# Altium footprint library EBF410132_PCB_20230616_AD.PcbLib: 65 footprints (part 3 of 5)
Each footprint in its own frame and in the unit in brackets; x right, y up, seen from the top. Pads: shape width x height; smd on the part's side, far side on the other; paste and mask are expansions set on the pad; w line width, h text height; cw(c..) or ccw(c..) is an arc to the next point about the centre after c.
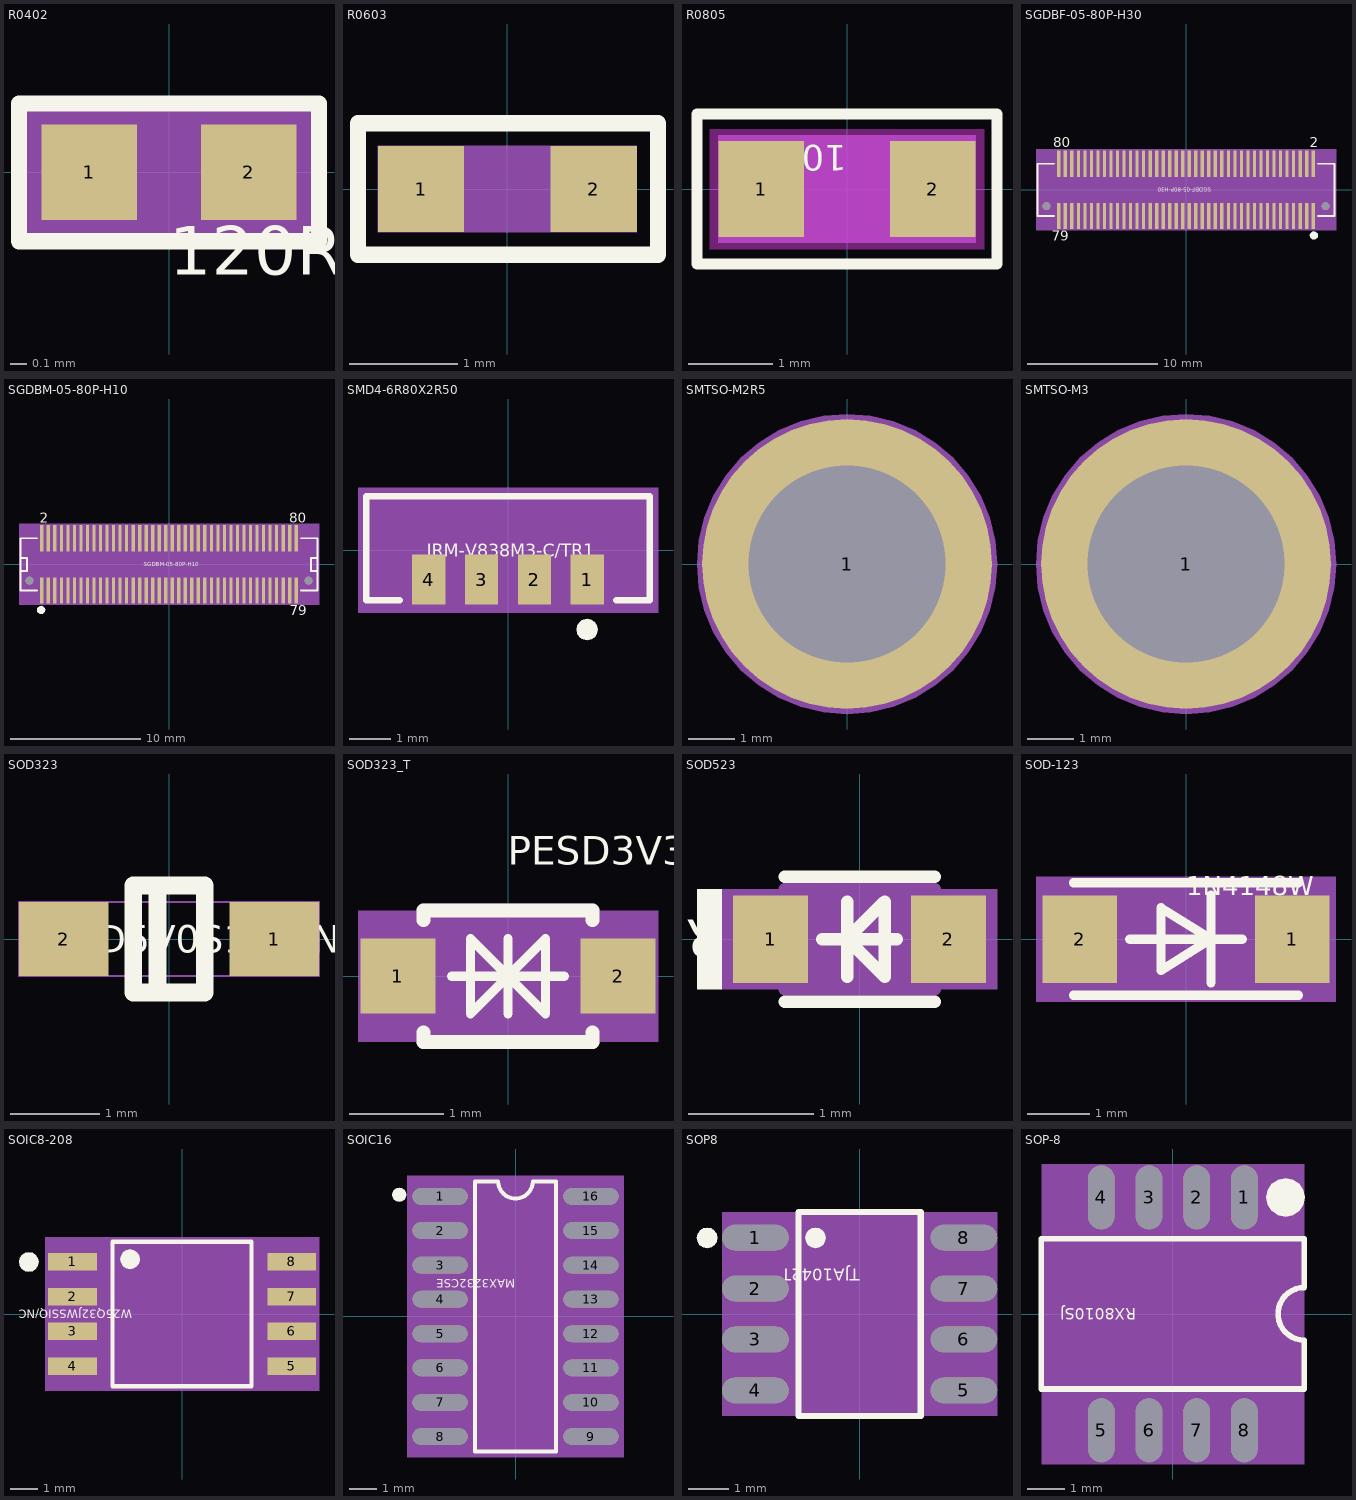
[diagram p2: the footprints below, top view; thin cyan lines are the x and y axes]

## R0402 [mm] "R0402"
pads (2):
  rect 0.599x0.599 smd: 1(-0.5,0) 2(0.5,0)
Top Overlay:
  lines w0.102: -0.94,-0.432 0.94,-0.432 0.94,0.432 -0.94,0.432 -0.94,-0.432
  text "120R" at 0,-0.64 h0.3
Top 3D Body:
  region: 0.94,0.432 0.94,-0.432 -0.94,-0.432 -0.94,0.432
Mechanical 15:
  text "2" at 0.5,-0.254 h0.64
  text "1" at -0.5,-0.254 h0.64
Top Assembly:
  dashed: -0.94,-0.432 -0.94,0.432 0.94,0.432 0.94,-0.432
3D body: height 3.81, standoff 0, extent -0.94,-0.432 0.94,0.432

## R0603 [mil] "R0603"
pads (2):
  rect 31.5x31.5 smd: 1(-31.5,0) 2(31.5,0)
Top Overlay:
  lines w6: -54.5,-24 55,-24 55,24 -54.5,24 -54.5,-24
  text "10K" at -14.4,6 h12
Top 3D Body:
  region: -47.24,-15.75 -47.24,15.75 47.24,15.75 47.24,-15.75
Mechanical 15:
  text "1" at -49.5,0 h45
  text "2" at 13.5,0 h45
3D body: height 150, standoff 0, extent -47.24,-15.75 47.24,15.75

## R0805 [mil] "R0805"
pads (2):
  rect 40x45 smd: 1(-40,0) 2(40,0)
Top Overlay:
  lines w5: -70,-35 70,-35 70,35 -70,35 -70,-35
  text "10R" at -0.01,20.4 h12
Top 3D Body:
  region: -60,25 60,25 60,-25 -60,-25
Mechanical 15:
  text "2" at 40,12 h30
  text "1" at -40,12 h30
Top Assembly:
  text "R0805" at -115,45 h25
Multi-Layer keep-out:
  region: -64,-28 -64,28 64,28 64,-28
3D body: height 150, standoff 0, extent -60,-25 60,25

## SGDBF-05-80P-H30 [mm] "SGDBF-05-80P-H30"
pads (82):
  rect 0.25x2 smd: 1(9.75,-2) 2(9.75,2) 3(9.25,-2) 4(9.25,2) 5(8.75,-2) 6(8.75,2) 7(8.25,-2) 8(8.25,2) 9(7.75,-2) 10(7.75,2) 11(7.25,-2) 12(7.25,2) 13(6.75,-2) 14(6.75,2) 15(6.25,-2) 16(6.25,2) 17(5.75,-2) 18(5.75,2) 19(5.25,-2) 20(5.25,2) 21(4.75,-2) 22(4.75,2) 23(4.25,-2) 24(4.25,2) 25(3.75,-2) 26(3.75,2) 27(3.25,-2) 28(3.25,2) 29(2.75,-2) 30(2.75,2) 31(2.25,-2) 32(2.25,2) 33(1.75,-2) 34(1.75,2) 35(1.25,-2) 36(1.25,2) 37(0.75,-2) 38(0.75,2) 39(0.25,-2) 40(0.25,2) 41(-0.25,-2) 42(-0.25,2) 43(-0.75,-2) 44(-0.75,2) 45(-1.25,-2) 46(-1.25,2) 47(-1.75,-2) 48(-1.75,2) 49(-2.25,-2) 50(-2.25,2) 51(-2.75,-2) 52(-2.75,2) 53(-3.25,-2) 54(-3.25,2) 55(-3.75,-2) 56(-3.75,2) 57(-4.25,-2) 58(-4.25,2) 59(-4.75,-2) 60(-4.75,2) 61(-5.25,-2) 62(-5.25,2) 63(-5.75,-2) 64(-5.75,2) 65(-6.25,-2) 66(-6.25,2) 67(-6.75,-2) 68(-6.75,2) 69(-7.25,-2) 70(-7.25,2) 71(-7.75,-2) 72(-7.75,2) 73(-8.25,-2) 74(-8.25,2) 75(-8.75,-2) 76(-8.75,2) 77(-9.25,-2) 78(-9.25,2) 79(-9.75,-2) 80(-9.75,2)
  round 0.6 hole 0.6 unplated: ""(-10.7,-1.25) ""(10.7,-1.25)
Top Overlay:
  dashed: 9.494,-3.5 9.517,-3.617 9.584,-3.716 9.683,-3.783 9.8,-3.806 9.917,-3.783 9.95,-3.76 10.016,-3.716 10.083,-3.617 10.106,-3.5 10.083,-3.383 10.016,-3.284 9.95,-3.24 9.917,-3.217 9.8,-3.194 9.683,-3.217 9.584,-3.284 9.517,-3.383
  lines w0.15: -10.1,-2 -11.4,-2 -11.4,2 -10.1,2 ; 10.1,-2 11.4,-2 11.4,2 10.1,2
  text "SGDBF-05-80P-H30" at 1.951,0.152 h0.3
  text "80" at -10.183,3.282 h0.76
  text "2" at 9.497,3.282 h0.76
  text "79" at -10.283,-3.917 h0.76
Top 3D Body:
  region: 11.5,-3.1 11.5,3.1 -11.5,3.1 -11.5,-3.1
Mechanical 15:
  text "15" at 6.758,-2 h0.64
  text "13" at 7.258,-2 h0.64
  text "17" at 6.258,-2 h0.64
  text "10" at 8.258,2 h0.64
  text "4" at 9.504,2 h0.64
  text "8" at 8.504,2 h0.64
  text "39" at 0.758,-2 h0.64
  text "56" at -3.242,2 h0.64
  text "59" at -4.242,-2 h0.64
  text "60" at -4.242,2 h0.64
  text "30" at 3.258,2 h0.64
  text "51" at -2.242,-2 h0.64
  text "44" at -0.242,2 h0.64
  text "37" at 1.258,-2 h0.64
  text "62" at -4.742,2 h0.64
  text "66" at -5.742,2 h0.64
  text "25" at 4.258,-2 h0.64
  text "27" at 3.758,-2 h0.64
  text "7" at 8.504,-2 h0.64
  text "68" at -6.242,2 h0.64
  text "9" at 8.004,-2 h0.64
  text "43" at -0.242,-2 h0.64
  text "12" at 7.758,2 h0.64
  text "33" at 2.258,-2 h0.64
  text "23" at 4.758,-2 h0.64
  text "79" at -9.242,-2 h0.64
  text "75" at -8.242,-2 h0.64
  text "77" at -8.742,-2 h0.64
  text "73" at -7.742,-2 h0.64
  text "71" at -7.242,-2 h0.64
  text "69" at -6.742,-2 h0.64
  text "1" at 10.004,-2 h0.64
  text "78" at -8.742,2 h0.64
  text "80" at -9.242,2 h0.64
  text "2" at 10.004,2 h0.64
  text "26" at 4.258,2 h0.64
  text "40" at 0.758,2 h0.64
  text "54" at -2.742,2 h0.64
  text "58" at -3.742,2 h0.64
  text "64" at -5.242,2 h0.64
  text "70" at -6.742,2 h0.64
  text "76" at -8.242,2 h0.64
  text "74" at -7.742,2 h0.64
  text "72" at -7.242,2 h0.64
  text "67" at -6.242,-2 h0.64
  text "61" at -4.742,-2 h0.64
  text "65" at -5.742,-2 h0.64
  text "11" at 7.758,-2 h0.64
  text "41" at 0.258,-2 h0.64
  text "57" at -3.742,-2 h0.64
  text "55" at -3.242,-2 h0.64
  text "53" at -2.742,-2 h0.64
  text "49" at -1.742,-2 h0.64
  text "21" at 5.258,-2 h0.64
  text "19" at 5.758,-2 h0.64
  text "5" at 9.004,-2 h0.64
  text "3" at 9.504,-2 h0.64
  text "45" at -0.742,-2 h0.64
  text "63" at -5.242,-2 h0.64
  text "42" at 0.258,2 h0.64
  text "46" at -0.742,2 h0.64
  text "48" at -1.242,2 h0.64
  text "50" at -1.742,2 h0.64
  text "52" at -2.242,2 h0.64
  text "38" at 1.258,2 h0.64
  text "36" at 1.758,2 h0.64
  text "28" at 3.758,2 h0.64
  text "32" at 2.758,2 h0.64
  text "34" at 2.258,2 h0.64
  text "47" at -1.242,-2 h0.64
  text "6" at 9.004,2 h0.64
  text "35" at 1.758,-2 h0.64
  text "31" at 2.758,-2 h0.64
  text "29" at 3.258,-2 h0.64
  text "24" at 4.758,2 h0.64
  text "22" at 5.258,2 h0.64
  text "20" at 5.758,2 h0.64
  text "18" at 6.258,2 h0.64
  text "16" at 6.758,2 h0.64
  text "14" at 7.258,2 h0.64
Top Assembly:
  lines w0.15: -11.4,-2 11.4,-2 11.4,2 -11.4,2 -11.4,-2
3D body: height 3.81, standoff 0, extent -11.5,-3.1 11.5,3.1

## SGDBM-05-80P-H10 [mm] "SGDBM-05-80P-H10"
pads (82):
  rect 0.25x2 smd: 1(-9.75,-2) 2(-9.75,2) 3(-9.25,-2) 4(-9.25,2) 5(-8.75,-2) 6(-8.75,2) 7(-8.25,-2) 8(-8.25,2) 9(-7.75,-2) 10(-7.75,2) 11(-7.25,-2) 12(-7.25,2) 13(-6.75,-2) 14(-6.75,2) 15(-6.25,-2) 16(-6.25,2) 17(-5.75,-2) 18(-5.75,2) 19(-5.25,-2) 20(-5.25,2) 21(-4.75,-2) 22(-4.75,2) 23(-4.25,-2) 24(-4.25,2) 25(-3.75,-2) 26(-3.75,2) 27(-3.25,-2) 28(-3.25,2) 29(-2.75,-2) 30(-2.75,2) 31(-2.25,-2) 32(-2.25,2) 33(-1.75,-2) 34(-1.75,2) 35(-1.25,-2) 36(-1.25,2) 37(-0.75,-2) 38(-0.75,2) 39(-0.25,-2) 40(-0.25,2) 41(0.25,-2) 42(0.25,2) 43(0.75,-2) 44(0.75,2) 45(1.25,-2) 46(1.25,2) 47(1.75,-2) 48(1.75,2) 49(2.25,-2) 50(2.25,2) 51(2.75,-2) 52(2.75,2) 53(3.25,-2) 54(3.25,2) 55(3.75,-2) 56(3.75,2) 57(4.25,-2) 58(4.25,2) 59(4.75,-2) 60(4.75,2) 61(5.25,-2) 62(5.25,2) 63(5.75,-2) 64(5.75,2) 65(6.25,-2) 66(6.25,2) 67(6.75,-2) 68(6.75,2) 69(7.25,-2) 70(7.25,2) 71(7.75,-2) 72(7.75,2) 73(8.25,-2) 74(8.25,2) 75(8.75,-2) 76(8.75,2) 77(9.25,-2) 78(9.25,2) 79(9.75,-2) 80(9.75,2)
  round 0.6 hole 0.6 unplated: ""(-10.7,-1.25) ""(10.7,-1.25)
Top Overlay:
  dashed: -9.494,-3.5 -9.517,-3.383 -9.584,-3.284 -9.683,-3.217 -9.8,-3.194 -9.917,-3.217 -9.95,-3.24 -10.016,-3.284 -10.083,-3.383 -10.106,-3.5 -10.083,-3.617 -10.016,-3.716 -9.95,-3.76 -9.917,-3.783 -9.8,-3.806 -9.683,-3.783 -9.584,-3.716 -9.517,-3.617
  lines w0.15: -11.4,0 -11.4,-0.5 -10.9,-0.5 -10.9,0.5 -11.4,0.5 ; -10.1,-2 -11.4,-2 -11.4,2 -10.1,2 ; 10.1,-2 11.4,-2 11.4,2 10.1,2 ; 11.4,0 11.4,-0.5 10.9,-0.5 10.9,0.5 11.4,0.5
  text "SGDBM-05-80P-H10" at -1.951,-0.152 h0.3
  text "2" at -9.903,3.182 h0.76
  text "79" at 9.268,-3.895 h0.76
  text "80" at 9.217,3.182 h0.76
Top 3D Body:
  region: -11.5,3.1 -11.5,-3.1 11.5,-3.1 11.5,3.1
Mechanical 15:
  text "32" at -2.758,2 h0.64
  text "34" at -2.258,2 h0.64
  text "36" at -1.758,2 h0.64
  text "38" at -1.258,2 h0.64
  text "50" at 1.742,2 h0.64
  text "52" at 2.242,2 h0.64
  text "54" at 2.742,2 h0.64
  text "56" at 3.242,2 h0.64
  text "28" at -3.758,2 h0.64
  text "26" at -4.258,2 h0.64
  text "24" at -4.758,2 h0.64
  text "22" at -5.258,2 h0.64
  text "62" at 4.742,2 h0.64
  text "60" at 4.242,2 h0.64
  text "15" at -6.758,-2 h0.64
  text "10" at -8.258,2 h0.64
  text "9" at -8.004,-2 h0.64
  text "7" at -8.504,-2 h0.64
  text "18" at -6.258,2 h0.64
  text "14" at -7.258,2 h0.64
  text "30" at -3.258,2 h0.64
  text "64" at 5.242,2 h0.64
  text "40" at -0.758,2 h0.64
  text "68" at 6.242,2 h0.64
  text "58" at 3.742,2 h0.64
  text "1" at -10.004,-2 h0.64
  text "79" at 9.242,-2 h0.64
  text "75" at 8.242,-2 h0.64
  text "11" at -7.758,-2 h0.64
  text "27" at -3.758,-2 h0.64
  text "41" at -0.258,-2 h0.64
  text "55" at 3.242,-2 h0.64
  text "69" at 6.742,-2 h0.64
  text "2" at -10.004,2 h0.64
  text "8" at -8.504,2 h0.64
  text "77" at 8.742,-2 h0.64
  text "20" at -5.758,2 h0.64
  text "59" at 4.242,-2 h0.64
  text "42" at -0.258,2 h0.64
  text "21" at -5.258,-2 h0.64
  text "48" at 1.242,2 h0.64
  text "66" at 5.742,2 h0.64
  text "46" at 0.742,2 h0.64
  text "71" at 7.242,-2 h0.64
  text "44" at 0.242,2 h0.64
  text "73" at 7.742,-2 h0.64
  text "17" at -6.258,-2 h0.64
  text "51" at 2.242,-2 h0.64
  text "53" at 2.742,-2 h0.64
  text "19" at -5.758,-2 h0.64
  text "43" at 0.242,-2 h0.64
  text "13" at -7.258,-2 h0.64
  text "45" at 0.742,-2 h0.64
  text "47" at 1.242,-2 h0.64
  text "25" at -4.258,-2 h0.64
  text "16" at -6.758,2 h0.64
  text "49" at 1.742,-2 h0.64
  text "23" at -4.758,-2 h0.64
  text "72" at 7.242,2 h0.64
  text "61" at 4.742,-2 h0.64
  text "63" at 5.242,-2 h0.64
  text "65" at 5.742,-2 h0.64
  text "67" at 6.242,-2 h0.64
  text "5" at -9.004,-2 h0.64
  text "3" at -9.504,-2 h0.64
  text "39" at -0.758,-2 h0.64
  text "33" at -2.258,-2 h0.64
  text "35" at -1.758,-2 h0.64
  text "31" at -2.758,-2 h0.64
  text "29" at -3.258,-2 h0.64
  text "76" at 8.242,2 h0.64
  text "37" at -1.258,-2 h0.64
  text "12" at -7.758,2 h0.64
  text "57" at 3.742,-2 h0.64
  text "80" at 9.242,2 h0.64
  text "78" at 8.742,2 h0.64
  text "70" at 6.742,2 h0.64
  text "4" at -9.504,2 h0.64
  text "6" at -9.004,2 h0.64
  text "74" at 7.742,2 h0.64
Top Assembly:
  lines w0.15: -11.4,-2 11.4,-2 11.4,2 -11.4,2 -11.4,-2
3D body: height 3.81, standoff 0, extent -11.5,-3.1 11.5,3.1

## SMD4-6R80X2R50 [mm] "SMD4-6R80X2R50"
pads (4):
  rect 0.8x1.2 smd: 1(1.905,-0.7) 2(0.635,-0.7) 3(-0.635,-0.7) 4(-1.905,-0.7)
Top Overlay:
  dashed: 2.155,-1.9 2.136,-1.802 2.08,-1.72 1.998,-1.664 1.9,-1.645 1.802,-1.664 1.775,-1.683 1.72,-1.72 1.664,-1.802 1.645,-1.9 1.664,-1.998 1.72,-2.08 1.775,-2.117 1.802,-2.136 1.9,-2.155 1.998,-2.136 2.08,-2.08 2.136,-1.998
  lines w0.15: -2.6,-1.2 -3.4,-1.2 -3.4,1.3 3.4,1.3 3.4,-1.2 2.6,-1.2
  text "IRM-V838M3-C/TR1" at -1.951,-0.152 h0.3
Top 3D Body:
  region: -3.6,1.5 -3.6,-1.5 3.6,-1.5 3.6,1.5
Mechanical 15:
  text "4" at -2.159,-0.7 h0.64
  text "1" at 1.651,-0.7 h0.64
  text "2" at 0.381,-0.7 h0.64
  text "3" at -0.889,-0.7 h0.64
Top Assembly:
  lines w0.15: -3.4,-1.2 3.4,-1.2 3.4,1.3 -3.4,1.3 -3.4,-1.2
3D body: height 3.81, standoff 0, extent -3.6,-1.5 3.6,1.5

## SMTSO-M2R5 [mm] "SMTSO-M2R5"
pads (1):
  round 6.2 / inner round 5.2 / far side round 5.2 hole 4.22: 1(0,0)
Top Overlay:
  text "M2.5X4mm" at -0.975,-0.152 h0.3
Top 3D Body:
  region: 3.21,0 3.17,0.502 3.053,0.992 2.86,1.457 2.597,1.887 2.27,2.27 1.887,2.597 1.457,2.86 0.992,3.053 0.502,3.17 0,3.21 -0.502,3.17 -0.992,3.053 -1.457,2.86 -1.601,2.772 -1.887,2.597 -2.27,2.27 -2.597,1.887 -2.86,1.457 -3.053,0.992 -3.17,0.502 -3.21,0 -3.17,-0.502 -3.053,-0.992 -2.86,-1.457 -2.597,-1.887 -2.27,-2.27 -1.887,-2.597 -1.601,-2.772 -1.457,-2.86 -0.992,-3.053 -0.502,-3.17 0,-3.21 0.502,-3.17 0.992,-3.053 1.457,-2.86 1.887,-2.597 2.27,-2.27 2.597,-1.887 2.86,-1.457 3.053,-0.992 3.17,-0.502
Mechanical 15:
  text "1" at -0.254,0 h0.64
3D body: height 3.81, standoff 0, extent -3.21,-3.21 3.21,3.21

## SMTSO-M3 [mm] "SMTSO-M3"
pads (1):
  round 6.2 / inner round 5.2 / far side round 5.2 hole 4.22: 1(0,0)
Top Overlay:
  text "M3X3.5mm" at -0.975,-0.152 h0.3
Top 3D Body:
  region: 3.21,0 3.17,0.502 3.053,0.992 2.86,1.457 2.597,1.887 2.27,2.27 1.887,2.597 1.457,2.86 0.992,3.053 0.502,3.17 0,3.21 -0.502,3.17 -0.992,3.053 -1.457,2.86 -1.601,2.772 -1.887,2.597 -2.27,2.27 -2.597,1.887 -2.86,1.457 -3.053,0.992 -3.17,0.502 -3.21,0 -3.17,-0.502 -3.053,-0.992 -2.86,-1.457 -2.597,-1.887 -2.27,-2.27 -1.887,-2.597 -1.601,-2.772 -1.457,-2.86 -0.992,-3.053 -0.502,-3.17 0,-3.21 0.502,-3.17 0.992,-3.053 1.457,-2.86 1.887,-2.597 2.27,-2.27 2.597,-1.887 2.86,-1.457 3.053,-0.992 3.17,-0.502
Mechanical 15:
  text "1" at -0.376,0 h0.94
3D body: height 3.81, standoff 0, extent -3.21,-3.21 3.21,3.21

## SOD323 [mm] "SOD323"
pads (2):
  rect 1x0.83 smd: 1(1.18,0) 2(-1.18,0)
Top Overlay:
  lines w0.2: -0.13,-0.6 -0.13,0.6 ; -0.4,-0.6 -0.4,0.6 0.4,0.6 0.4,-0.6 -0.4,-0.6
  text "PESD5V0S1BA-N" at -1.585,-0.152 h0.3
Top 3D Body:
  lines w0.025: -1.68,-0.415 1.68,-0.415 1.68,0.415 -1.68,0.415 -1.68,-0.415
Mechanical 15:
  text "1" at 1.058,0 h0.3
  text "2" at -1.302,0 h0.3

## SOD323_T [mm] "SOD323_T"
pads (2):
  rect 0.8x0.8 smd: 1(-1.175,0) 2(1.175,0)
Top Overlay:
  lines w0.1: -0.6,0 0.6,0 ; 0,-0.4 0,0.4 ; 0,0 -0.4,-0.4 -0.4,0.4 0,0 ; 0,0 0.4,0.4 0.4,-0.4 0,0
  lines w0.15: -0.9,-0.6 -0.9,-0.7 0.9,-0.7 0.9,-0.6 ; -0.9,0.6 -0.9,0.7 0.9,0.7 0.9,0.6
  text "PESD3V3L1BA" at 0,1.189 h0.3
Top 3D Body:
  region: -1.6,0.7 -1.6,-0.7 1.6,-0.7 1.6,0.7
Mechanical 15:
  text "2" at 1.175,0.254 h0.64
  text "1" at -1.175,0.254 h0.64
Top Assembly:
  lines w0.15: -0.9,-0.7 0.9,-0.7 0.9,0.7 -0.9,0.7 -0.9,-0.7
3D body: height 3.81, standoff 0, extent -1.6,-0.7 1.6,0.7

## SOD523 [mm] "SOD523"
pads (2):
  rect 0.6x0.7 smd: 1(-0.71,0) 2(0.71,0)
Top Overlay:
  dashed: -1.3,0.4 -1.3,-0.4 -1.1,-0.4 -1.1,0.4
  lines w0.1: -0.6,-0.5 0.6,-0.5 ; -0.6,0.5 0.6,0.5 ; -0.3,0 0.3,0 ; -0.1,-0.3 -0.1,0.3 ; -0.1,0 0.2,0.3 0.2,-0.3 -0.1,0
  text "RB521S-30" at -1.097,0.152 h0.3
Top 3D Body:
  region: -1.1,0.4 -1.1,-0.4 1.1,-0.4 1.1,0.4
Mechanical 15:
  text "1" at -0.964,0 h0.64
  text "2" at 0.456,0 h0.64
Top Assembly:
  lines w0.1: -0.6,-0.4 0.6,-0.4 0.6,0.4 -0.6,0.4 -0.6,-0.4
3D body: height 3.81, standoff 0, extent -1.1,-0.4 1.1,0.4

## SOD-123 [mm] "SOD-123"
pads (2):
  rect 1.2x1.4 smd: 1(1.7,0) 2(-1.7,0)
Top Overlay:
  lines w0.15: -1.8,-0.9 1.8,-0.9 ; -1.8,0.9 1.8,0.9 ; -0.9,0 0.9,0 ; 0.4,-0.7 0.4,0.7 ; -0.4,-0.5 -0.4,0.5 0.4,0 -0.4,-0.5
  text "1N4148W" at 0,0.701 h0.3
Top 3D Body:
  region: -2.4,-1 2.4,-1 2.4,1 -2.4,1
Mechanical 15:
  text "1" at 1.7,0.315 h0.79
  text "2" at -1.7,0.315 h0.79
Top Assembly:
  lines w0.15: -1.8,-0.9 1.8,-0.9 1.8,0.9 -1.8,0.9 -1.8,-0.9
3D body: height 3.81, standoff 0, extent -2.4,-1 2.4,1

## SOIC8-208 [mm] "SOIC8-208"
pads (8):
  rect 1.778x0.635 smd: 1(-4,1.905) 2(-4,0.635) 3(-4,-0.635) 4(-4,-1.905) 5(4,-1.905) 6(4,-0.635) 7(4,0.635) 8(4,1.905)
Top Overlay:
  dashed: -5.243,1.9 -5.27,1.763 -5.348,1.648 -5.463,1.57 -5.6,1.543 -5.737,1.57 -5.775,1.596 -5.852,1.648 -5.93,1.763 -5.957,1.9 -5.93,2.037 -5.852,2.152 -5.775,2.204 -5.737,2.23 -5.6,2.257 -5.463,2.23 -5.348,2.152 -5.27,2.037
  dashed: -1.543,2 -1.57,1.863 -1.648,1.748 -1.763,1.67 -1.9,1.643 -2.037,1.67 -2.075,1.696 -2.152,1.748 -2.23,1.863 -2.257,2 -2.23,2.137 -2.152,2.252 -2.075,2.304 -2.037,2.33 -1.9,2.357 -1.763,2.33 -1.648,2.252 -1.57,2.137
  lines w0.152: -2.54,-2.64 2.54,-2.64 2.54,2.64 -2.54,2.64 -2.54,-2.64
  text "W25Q32JWSSIQ/NC" at -1.829,0.152 h0.3
Top 3D Body:
  region: -5,2.8 -5,-2.8 5,-2.8 5,2.8
Mechanical 15:
  text "4" at -4.203,-1.905 h0.51
  text "8" at 3.797,1.905 h0.51
  text "7" at 3.797,0.635 h0.51
  text "5" at 3.797,-1.905 h0.51
  text "2" at -4.203,0.635 h0.51
  text "1" at -4.203,1.905 h0.51
  text "6" at 3.797,-0.635 h0.51
  text "3" at -4.203,-0.635 h0.51
Top Assembly:
  lines w0.152: -2.54,-2.64 2.54,-2.64 2.54,2.64 -2.54,2.64 -2.54,-2.64
3D body: height 3.81, standoff 0, extent -5,-2.8 5,2.8

## SOIC16 [mil] "SOIC16"
pads (16):
  oval 80x24 smd: 1(-109.8,174.8) 2(-109.8,125.2) 3(-109.8,74.8) 4(-109.8,25.2) 5(-109.8,-25.2) 6(-109.8,-74.8) 7(-109.8,-125.2) 8(-109.8,-174.8) 9(109.8,-174.8) 10(109.8,-125.2) 11(109.8,-74.8) 12(109.8,-25.2) 13(109.8,25.2) 14(109.8,74.8) 15(109.8,125.2) 16(109.8,174.8)
Top Overlay:
  dashed: -169.29,167.13 -173.13,167.89 -176.39,170.07 -178.56,173.32 -179.33,177.16 -178.56,181.01 -177.83,182.1 -176.39,184.26 -173.13,186.44 -169.29,187.2 -165.45,186.44 -162.2,184.26 -160.75,182.1 -160.02,181.01 -159.26,177.16 -160.02,173.32 -162.2,170.07 -165.45,167.89
  lines w5.91: -59.05,-196.85 -59.05,196.85 -39.37,196.85 -25.2,196.85 ccw(c0,196.85) 25.2,196.85 59.05,196.85 59.05,-196.85 -59.05,-196.85
  text "MAX3232CSE" at -0.01,54 h12
Top 3D Body:
  region: -157.48,204.72 -157.48,-204.72 157.48,-204.72 157.48,204.72
Mechanical 15:
  text "16" at 109.8,184.4 h12
  text "4" at -109.8,30 h12
  text "5" at -109.8,-20.4 h12
  text "2" at -109.8,130 h12
  text "6" at -109.8,-70 h12
  text "1" at -109.8,179.6 h12
  text "3" at -109.8,79.6 h12
  text "15" at 109.8,134.8 h12
  text "9" at 109.8,-170 h12
  text "10" at 109.8,-115.6 h12
  text "11" at 109.8,-65.2 h12
  text "12" at 109.8,-15.6 h12
  text "14" at 109.8,84.4 h12
  text "13" at 109.8,34.8 h12
  text "7" at -109.8,-120.4 h12
  text "8" at -109.8,-170 h12
3D body: height 150, standoff 0, extent -157.48,-204.72 157.48,204.72

## SOP8 [mil] "SOP8"
pads (8):
  oval 65x25 smd: 1(-102.36,75) 2(-102.36,25) 3(-102.36,-25) 4(-102.36,-75) 5(102.36,-75) 6(102.36,-25) 7(102.36,25) 8(102.36,75)
Top Overlay:
  dashed: -149.61,64.77 -153.45,65.53 -156.7,67.71 -158.88,70.96 -159.64,74.8 -158.88,78.64 -158.15,79.73 -156.7,81.9 -153.45,84.07 -149.61,84.84 -145.77,84.07 -142.51,81.9 -141.07,79.73 -140.34,78.64 -139.57,74.8 -140.34,70.96 -142.51,67.71 -145.77,65.53
  dashed: -43.31,64.77 -47.15,65.53 -50.4,67.71 -52.58,70.96 -53.34,74.8 -52.58,78.64 -51.85,79.73 -50.4,81.9 -47.15,84.07 -43.31,84.84 -39.47,84.07 -36.21,81.9 -34.77,79.73 -34.04,78.64 -33.27,74.8 -34.04,70.96 -36.21,67.71 -39.47,65.53
  lines w6: -60,-100 -60,100 60,100 60,-100 -60,-100
  text "TJA1042T" at -0.01,44.4 h12
Top 3D Body:
  region: -134.86,-100 134.86,-100 134.86,100 -134.86,100
Mechanical 15:
  text "5" at 102.36,-65 h25
  text "2" at -102.36,35 h25
  text "8" at 102.36,85 h25
  text "6" at 102.36,-15 h25
  text "1" at -102.36,85 h25
  text "4" at -102.36,-65 h25
  text "7" at 102.36,35 h25
  text "3" at -102.36,-15 h25
3D body: height 150, standoff 0, extent -134.86,-100 134.86,100

## SOP-8 [mm] "SOP-8"
pads (8):
  oval 0.7x1.7 smd: 1(1.903,3.104) 2(0.633,3.104) 3(-0.637,3.104) 4(-1.907,3.104) 5(-1.907,-3.096) 6(-0.637,-3.096) 7(0.633,-3.096) 8(1.903,-3.096)
Top Overlay:
  dashed: 3.508,3.104 3.469,2.909 3.359,2.743 3.193,2.633 2.998,2.594 2.803,2.633 2.748,2.67 2.638,2.743 2.527,2.909 2.489,3.104 2.527,3.299 2.638,3.464 2.748,3.538 2.803,3.575 2.998,3.614 3.193,3.575 3.359,3.464 3.469,3.299
  lines w0.15: -3.502,-1.996 -3.502,2.004 3.498,2.004 3.498,0.704 ccw(c3.498,0.004) 3.498,-0.696 3.498,-1.996 -3.502,-1.996
  text "RX8010SJ" at -0.975,0.152 h0.3
Top 3D Body:
  region: -3.498,3.994 -3.498,-3.994 3.498,-3.994 3.498,3.994
Mechanical 15:
  text "4" at -2.079,3.104 h0.43
  text "5" at -2.079,-3.096 h0.43
  text "6" at -0.809,-3.096 h0.43
  text "7" at 0.461,-3.096 h0.43
  text "8" at 1.731,-3.096 h0.43
  text "2" at 0.461,3.104 h0.43
  text "1" at 1.731,3.104 h0.43
  text "3" at -0.809,3.104 h0.43
3D body: height 3.81, standoff 0, extent -3.498,-3.994 3.498,3.994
